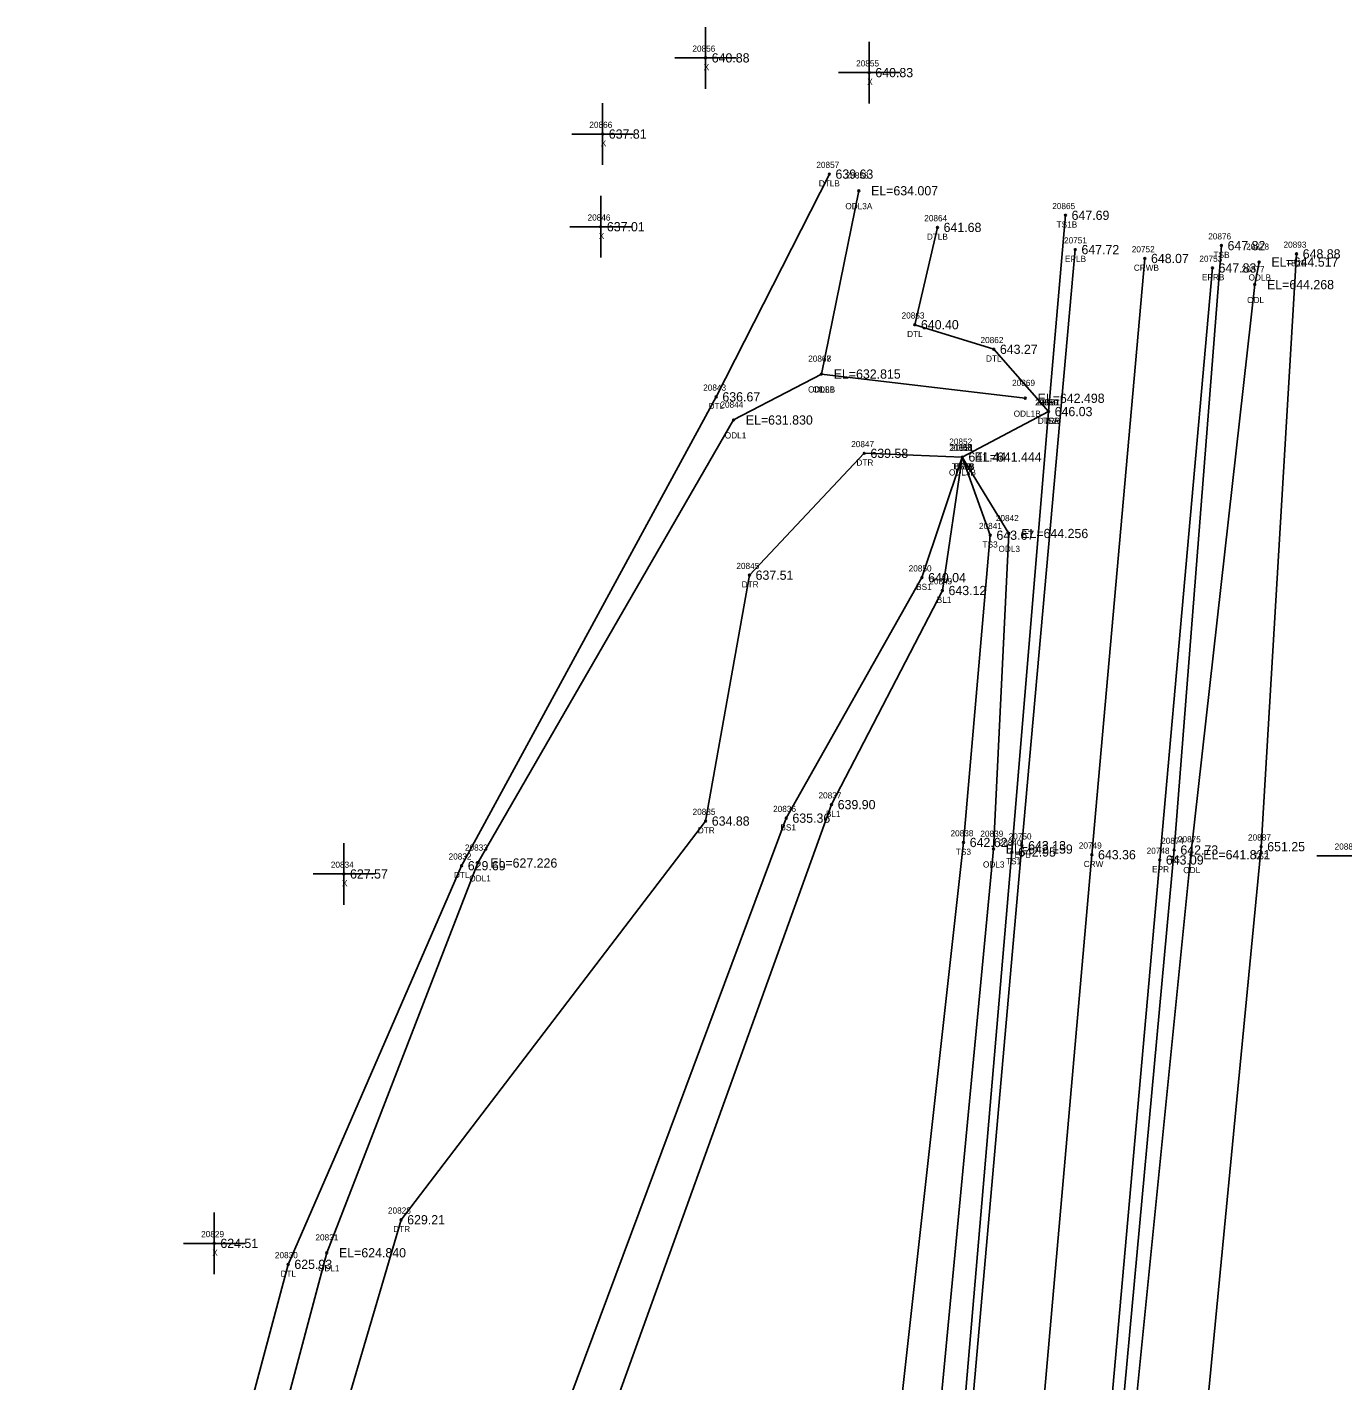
# Model space of a CAD drawing. Extents: x 1695443 to 1696344, y 1087542 to 1090645.
# Drawn here: x 1695706.6 to 1695920.2, y 1090424.7 to 1090644.5 of the extents above; entities that cross this region are included whole.
import ezdxf

# ---------------------------------------------------------------- set-up
doc = ezdxf.new("R2010")
doc.units = 0
for name, color, linetype in [('RD_DTM_BkLn1', 7, 'Continuous'), ('RD_DTM_BkLn2', 7, 'Continuous'), ('RD_DTM_BkLn_txCode', 7, 'Continuous'), ('RD_EX_H2O', 7, 'Continuous'), ('RD_EX_H2O_txCode', 7, 'Continuous'), ('RD_EX_Misc', 7, 'Continuous'), ('RD_EX_Misc_txCode', 7, 'Continuous'), ('RD_EX_Road', 7, 'Continuous'), ('RD_EX_Road_txCode', 7, 'Continuous'), ('RD_EX_TX_H2O_ELEV', 7, 'Continuous'), ('RD_EX_TX_Misc_ELEV', 7, 'Continuous'), ('RD_EX_TX_Road_ELEV', 7, 'Continuous'), ('RD_HC_Survey_ELEV', 7, 'Continuous'), ('RD_HC_Survey_txCode', 7, 'Continuous'), ('RD_SMD_Locator', 7, 'Continuous')]:
    doc.layers.add(name, color=color, linetype=linetype)

msp = doc.modelspace()

# ---------------------------------------------------------------- linework, layer by layer
at = {"layer": 'RD_DTM_BkLn1'}
for points in [[(1695813.78, 1089148.1), (1695785.55, 1089189.03), (1695758.89, 1089235.87), (1695740.64, 1089279.02), (1695725.17, 1089334.02), (1695718.27, 1089382.65), (1695717.41, 1089435.13), (1695722.03, 1089482.62), (1695732.64, 1089534.75), (1695759.85, 1089631.43), (1695787.11, 1089727.89), (1695798.89, 1089774.41), (1695810.31, 1089824.5), (1695818.49, 1089870.61), (1695825.85, 1089922.33), (1695831.69, 1089976.57), (1695835.49, 1090019.27), (1695844.06, 1090117.91), (1695852.56, 1090215.73), (1695861.78, 1090313.02), (1695870.8, 1090411.68), (1695879.44, 1090510.15), (1695888.04, 1090606.94)], [(1695751.04, 1090219.89), (1695791.94, 1090244.82), (1695767.34, 1090324.95), (1695800.6, 1090416.81), (1695837.18, 1090518.29), (1695855.17, 1090553.04), (1695858.41, 1090574.71)]]:
    msp.add_lwpolyline(points, dxfattribs=at)
at = {"layer": 'RD_DTM_BkLn2'}
for points in [[(1695816.55, 1089985.57), (1695822.06, 1090019.33), (1695830.08, 1090118.98), (1695839.03, 1090218.11), (1695848.5, 1090314.54), (1695858.08, 1090412.43), (1695866.47, 1090510.6), (1695872.4, 1090582.09), (1695875.15, 1090613.95)], [(1695859.8, 1090070.52), (1695855.89, 1090074.82), (1695858.76, 1090117.78), (1695865.52, 1090214.74), (1695874.78, 1090312.49), (1695883.57, 1090410.43), (1695892.81, 1090510.92), (1695900.47, 1090609.03)], [(1695859.8, 1090070.52), (1695863.31, 1090073.64), (1695869.86, 1090116.28), (1695876.76, 1090213.36), (1695888.73, 1090306.44), (1695897.16, 1090410.32), (1695906.91, 1090511.46), (1695912.67, 1090607.68)], [(1695751.04, 1090219.89), (1695779.04, 1090246.96), (1695759.36, 1090326.31), (1695793.36, 1090418.3), (1695829.83, 1090516.09), (1695851.86, 1090555.13), (1695858.41, 1090574.71)], [(1695816.55, 1089985.57), (1695816.58, 1090019.89), (1695824.64, 1090119.16), (1695834.2, 1090219.01), (1695837.98, 1090315.44), (1695847.83, 1090415.25), (1695858.61, 1090512.14), (1695862.95, 1090562.02), (1695858.41, 1090574.71)]]:
    msp.add_lwpolyline(points, dxfattribs=at)
at = {"layer": 'RD_EX_H2O'}
msp.add_line((1695841.6, 1090617.93), (1695835.53, 1090588.18), dxfattribs=at)
for points in [[(1695706.84, 1090232.08), (1695721.27, 1090207.48), (1695724.07, 1090225.45), (1695728.53, 1090239.62), (1695741.98, 1090247.74), (1695743.59, 1090251.5), (1695720.64, 1090337.79), (1695748.97, 1090443.66), (1695777.13, 1090508.37), (1695818.46, 1090584.48), (1695836.82, 1090620.63)], [(1695872.4, 1090582.09), (1695863.51, 1090592.2), (1695850.69, 1090596.19), (1695854.37, 1090611.98)], [(1695860.52, 1090075.19), (1695864.26, 1090116.99), (1695868.56, 1090214.89), (1695876.96, 1090312.57), (1695885.5, 1090410.04), (1695895.53, 1090510.16), (1695905.88, 1090602.7), (1695906.59, 1090606.36)], [(1695742.01, 1090022.28), (1695741.79, 1090065.32), (1695727.64, 1090116.67), (1695728.4, 1090182.12), (1695739.32, 1090221.09), (1695746.13, 1090251.36), (1695744.91, 1090257.64), (1695725.79, 1090335.12), (1695755.22, 1090445.54), (1695779.78, 1090508.81), (1695821.26, 1090580.72), (1695835.53, 1090588.18), (1695868.63, 1090584.25)], [(1695748.39, 1090023.09), (1695750.06, 1090066.34), (1695732.27, 1090115.98), (1695751.04, 1090219.89), (1695755.24, 1090253.72), (1695734.04, 1090337.88), (1695767.29, 1090450.9), (1695816.74, 1090515.62), (1695823.85, 1090555.53), (1695842.49, 1090575.31), (1695858.41, 1090574.71), (1695872.4, 1090582.09)], [(1695816.55, 1089985.57), (1695820.09, 1090019.62), (1695827.87, 1090118.57), (1695837.5, 1090218.61), (1695845.63, 1090315.02), (1695854.17, 1090413.34), (1695863.46, 1090511.07), (1695865.97, 1090562.3), (1695858.41, 1090574.71)]]:
    msp.add_lwpolyline(points, dxfattribs=at)
at = {"layer": 'RD_EX_Misc'}
for p, q in [((1695816.73, 1090634.5), (1695816.73, 1090644.5)), ((1695843.29, 1090632.11), (1695843.29, 1090642.11)), ((1695811.73, 1090639.5), (1695821.73, 1090639.5)), ((1695838.29, 1090637.11), (1695848.29, 1090637.11)), ((1695800.02, 1090622.14), (1695800.02, 1090632.14)), ((1695795.02, 1090627.14), (1695805.02, 1090627.14)), ((1695799.71, 1090607.09), (1695799.71, 1090617.09)), ((1695794.71, 1090612.09), (1695804.71, 1090612.09)), ((1695758.01, 1090502.03), (1695758.01, 1090512.03)), ((1695915.97, 1090509.98), (1695925.97, 1090509.98)), ((1695753.01, 1090507.03), (1695763.01, 1090507.03)), ((1695736.96, 1090442.07), (1695736.96, 1090452.07)), ((1695731.96, 1090447.07), (1695741.96, 1090447.07))]:
    msp.add_line(p, q, dxfattribs=at)
at = {"layer": 'RD_EX_Road'}
for points in [[(1695813.78, 1089148.1), (1695805.56, 1089142.08), (1695776.44, 1089183.94), (1695749.27, 1089231.88), (1695730.49, 1089275.72), (1695714.87, 1089332.12), (1695707.87, 1089381.72), (1695706.58, 1089435.34), (1695711.58, 1089484.26), (1695722.15, 1089537.59), (1695749.04, 1089634.88), (1695776.11, 1089730.43), (1695788.13, 1089777.42), (1695798.89, 1089826.76), (1695807.1, 1089870.03), (1695814.71, 1089923.3), (1695820.51, 1089978.16), (1695824.04, 1090019.79), (1695832.76, 1090119.06), (1695841.25, 1090216.76), (1695850.36, 1090314.41), (1695859.24, 1090411.82), (1695868.09, 1090511.63), (1695876.75, 1090608.38)], [(1695728.69, 1089383.6), (1695727.9, 1089434.83), (1695732.68, 1089480.1), (1695743.4, 1089531.84), (1695770.35, 1089628.36), (1695797.63, 1089725.22), (1695809.49, 1089772.37), (1695818.34, 1089811.57), (1695820.65, 1089823.41), (1695822.99, 1089835.26), (1695829.18, 1089869.37), (1695836.32, 1089920.97), (1695842.44, 1089975.46), (1695846.49, 1090018.55), (1695849.32, 1090055.39), (1695850.91, 1090072.92), (1695855.09, 1090117.49), (1695863.53, 1090214.93), (1695872.56, 1090312.44), (1695881.69, 1090410.78), (1695890.45, 1090509.3), (1695899.01, 1090605.4)]]:
    msp.add_lwpolyline(points, dxfattribs=at)
at = {"layer": 'RD_SMD_Locator'}
for centre in [(1695816.73, 1090639.5), (1695843.29, 1090637.11), (1695800.02, 1090627.14), (1695836.82, 1090620.63), (1695841.6, 1090617.93), (1695875.15, 1090613.95), (1695799.71, 1090612.09), (1695854.37, 1090611.98), (1695876.75, 1090608.38), (1695900.47, 1090609.03), (1695888.04, 1090606.94), (1695906.59, 1090606.36), (1695912.67, 1090607.68), (1695899.01, 1090605.4), (1695905.88, 1090602.7), (1695850.69, 1090596.19), (1695863.51, 1090592.2), (1695835.53, 1090588.18), (1695835.53, 1090588.18), (1695818.46, 1090584.48), (1695868.63, 1090584.25), (1695872.4, 1090582.09), (1695872.4, 1090582.09), (1695872.4, 1090582.09), (1695821.26, 1090580.72), (1695842.49, 1090575.31), (1695858.41, 1090574.71), (1695858.41, 1090574.71), (1695858.41, 1090574.71), (1695858.41, 1090574.71), (1695858.41, 1090574.71), (1695862.95, 1090562.02), (1695865.97, 1090562.3), (1695823.85, 1090555.53), (1695851.86, 1090555.13), (1695855.17, 1090553.04), (1695837.18, 1090518.29), (1695816.74, 1090515.62), (1695829.83, 1090516.09), (1695858.61, 1090512.14), (1695868.09, 1090511.63), (1695906.91, 1090511.46), (1695863.46, 1090511.07), (1695866.47, 1090510.6), (1695879.44, 1090510.15), (1695890.45, 1090509.3), (1695892.81, 1090510.92), (1695895.53, 1090510.16), (1695758.01, 1090507.03), (1695777.13, 1090508.37), (1695779.78, 1090508.81), (1695767.29, 1090450.9), (1695736.96, 1090447.07), (1695755.22, 1090445.54), (1695748.97, 1090443.66)]:
    msp.add_circle(centre, 0.15, dxfattribs=at)

# ---------------------------------------------------------------- texts
at = {"layer": 'RD_DTM_BkLn_txCode'}
for s, p in [('20865', (1695873.01, 1090614.95)), ('TS1B', (1695873.72, 1090611.95)), ('20876', (1695898.33, 1090610.03)), ('TSB', (1695899.2, 1090607.03)), ('20893', (1695910.55, 1090608.68)), ('TS2B', (1695910.95, 1090605.68)), ('20860', (1695870.22, 1090583.09)), ('TS1', (1695871.44, 1090580.09)), ('20853', (1695856.29, 1090575.71)), ('20854', (1695856.29, 1090575.71)), ('20851', (1695856.57, 1090575.71)), ('TS3B', (1695856.69, 1090572.71)), ('BS1B', (1695856.99, 1090572.71)), ('BL1B', (1695857.01, 1090572.71)), ('20841', (1695861.11, 1090563.02)), ('TS3', (1695861.7, 1090560.02)), ('20850', (1695849.7, 1090556.13)), ('BS1', (1695850.91, 1090553.13)), ('20849', (1695853.05, 1090554.04)), ('BL1', (1695854.25, 1090551.04)), ('20837', (1695835.06, 1090519.29)), ('20836', (1695827.69, 1090517.09)), ('BL1', (1695836.26, 1090516.29)), ('BS1', (1695828.88, 1090514.09)), ('20838', (1695856.49, 1090513.14)), ('20887', (1695904.79, 1090512.46)), ('20840', (1695864.31, 1090511.6)), ('20874', (1695890.69, 1090511.92)), ('TS3', (1695857.37, 1090510.14)), ('TS1', (1695865.51, 1090508.6)), ('TS', (1695892.02, 1090508.92)), ('TS2', (1695905.66, 1090509.46))]:
    msp.add_text(s, height=1, dxfattribs=at).set_placement(p)
at = {"layer": 'RD_EX_H2O_txCode'}
for s, p in [('20857', (1695834.71, 1090621.63)), ('DTLB', (1695835.11, 1090618.63)), ('20858', (1695839.48, 1090619.93)), ('ODL3A', (1695839.42, 1090614.93)), ('20864', (1695852.23, 1090612.98)), ('DTLB', (1695852.65, 1090609.98)), ('20878', (1695904.48, 1090608.36)), ('20877', (1695903.76, 1090604.7)), ('ODLB', (1695904.88, 1090603.36)), ('ODL', (1695904.64, 1090599.7)), ('20863', (1695848.55, 1090597.19)), ('DTL', (1695849.45, 1090594.19)), ('20862', (1695861.36, 1090593.2)), ('20867', (1695833.39, 1090590.18)), ('20868', (1695833.39, 1090590.18)), ('DTL', (1695862.26, 1090590.2)), ('20843', (1695816.34, 1090585.48)), ('ODL3B', (1695833.37, 1090585.18)), ('ODL1', (1695834.12, 1090585.18)), ('20869', (1695866.49, 1090586.25)), ('20859', (1695870.28, 1090583.09)), ('20861', (1695870.54, 1090583.09)), ('DTL', (1695817.21, 1090582.48)), ('20844', (1695819.14, 1090582.72)), ('ODL1B', (1695866.75, 1090581.25)), ('DTRB', (1695870.66, 1090580.09)), ('DTLA', (1695870.67, 1090580.09)), ('ODL1', (1695819.85, 1090577.72)), ('20847', (1695840.37, 1090576.31)), ('20852', (1695856.29, 1090576.71)), ('20848', (1695856.29, 1090575.71)), ('DTR', (1695841.22, 1090573.31)), ('DTR', (1695857.14, 1090572.71)), ('ODL3B', (1695856.24, 1090571.71)), ('20842', (1695863.85, 1090564.3)), ('ODL3', (1695864.28, 1090559.3)), ('20845', (1695821.73, 1090556.53)), ('DTR', (1695822.59, 1090553.53)), ('20835', (1695814.62, 1090516.62)), ('DTR', (1695815.47, 1090513.62)), ('20839', (1695861.34, 1090513.07)), ('20833', (1695777.66, 1090510.81)), ('20875', (1695893.41, 1090512.16)), ('20832', (1695775.01, 1090509.37)), ('ODL3', (1695861.76, 1090508.07)), ('DTL', (1695775.88, 1090506.37)), ('ODL', (1695894.28, 1090507.16)), ('ODL1', (1695778.37, 1090505.81)), ('20828', (1695765.17, 1090451.9)), ('DTR', (1695766.02, 1090448.9)), ('20831', (1695753.39, 1090447.54)), ('20830', (1695746.81, 1090444.66)), ('ODL1', (1695753.81, 1090442.54)), ('DTL', (1695747.72, 1090441.66))]:
    msp.add_text(s, height=1, dxfattribs=at).set_placement(p)
at = {"layer": 'RD_EX_Misc_txCode'}
for s, p in [('20856', (1695814.59, 1090640.5)), ('20855', (1695841.17, 1090638.11)), ('X', (1695816.42, 1090637.5)), ('X', (1695842.97, 1090635.11)), ('20866', (1695797.86, 1090628.14)), ('X', (1695799.71, 1090625.14)), ('20846', (1695797.57, 1090613.09)), ('X', (1695799.4, 1090610.09)), ('20888', (1695918.85, 1090510.98)), ('20834', (1695755.89, 1090508.03)), ('X', (1695757.7, 1090505.03)), ('20829', (1695734.84, 1090448.07)), ('X', (1695736.64, 1090445.07))]:
    msp.add_text(s, height=1, dxfattribs=at).set_placement(p)
at = {"layer": 'RD_EX_Road_txCode'}
for s, p in [('20751', (1695874.92, 1090609.38)), ('EPLB', (1695875.08, 1090606.38)), ('20753', (1695896.89, 1090606.4)), ('EPRB', (1695897.31, 1090603.4)), ('20750', (1695865.93, 1090512.63)), ('20748', (1695888.33, 1090510.3)), ('EPL', (1695866.89, 1090509.63)), ('EPR', (1695889.22, 1090507.3))]:
    msp.add_text(s, height=1, dxfattribs=at).set_placement(p)
at = {"layer": 'RD_EX_TX_H2O_ELEV'}
for s, p in [('639.63', (1695837.82, 1090619.88)), ('EL=634.007', (1695843.6, 1090617.18)), ('641.68', (1695855.37, 1090611.23)), ('EL=644.517', (1695908.59, 1090605.61)), ('EL=644.268', (1695907.88, 1090601.95)), ('640.40', (1695851.69, 1090595.44)), ('643.27', (1695864.51, 1090591.45)), ('EL=632.815', (1695837.53, 1090587.43)), ('EL=632.815', (1695837.53, 1090587.43)), ('636.67', (1695819.46, 1090583.73)), ('EL=642.498', (1695870.63, 1090583.5)), ('646.03', (1695873.4, 1090581.34)), ('646.03', (1695873.4, 1090581.34)), ('EL=631.830', (1695823.26, 1090579.97)), ('639.58', (1695843.49, 1090574.56)), ('641.44', (1695859.41, 1090573.96)), ('EL=641.444', (1695860.41, 1090573.96)), ('EL=644.256', (1695867.97, 1090561.55)), ('637.51', (1695824.85, 1090554.78)), ('634.88', (1695817.74, 1090514.87)), ('EL=642.159', (1695865.46, 1090510.32)), ('629.69', (1695778.13, 1090507.62)), ('EL=627.226', (1695781.78, 1090508.06)), ('EL=641.821', (1695897.53, 1090509.41)), ('629.21', (1695768.29, 1090450.15)), ('EL=624.840', (1695757.22, 1090444.79)), ('625.93', (1695749.97, 1090442.91))]:
    msp.add_text(s, height=1.5, dxfattribs=at).set_placement(p)
at = {"layer": 'RD_EX_TX_Misc_ELEV'}
for s, p in [('640.88', (1695817.73, 1090638.75)), ('640.83', (1695844.29, 1090636.36)), ('637.81', (1695801.02, 1090626.39)), ('647.69', (1695876.15, 1090613.2)), ('637.01', (1695800.71, 1090611.34)), ('647.82', (1695901.47, 1090608.28)), ('648.88', (1695913.67, 1090606.93)), ('646.03', (1695873.4, 1090581.34)), ('641.44', (1695859.41, 1090573.96)), ('641.44', (1695859.41, 1090573.96)), ('641.44', (1695859.41, 1090573.96)), ('643.67', (1695863.95, 1090561.27)), ('640.04', (1695852.86, 1090554.38)), ('643.12', (1695856.17, 1090552.29)), ('639.90', (1695838.18, 1090517.54)), ('635.36', (1695830.83, 1090515.34)), ('642.62', (1695859.61, 1090511.39)), ('642.95', (1695867.47, 1090509.85)), ('642.73', (1695893.81, 1090510.17)), ('651.25', (1695907.91, 1090510.71)), ('627.57', (1695759.01, 1090506.28)), ('624.51', (1695737.96, 1090446.32))]:
    msp.add_text(s, height=1.5, dxfattribs=at).set_placement(p)
at = {"layer": 'RD_EX_TX_Road_ELEV'}
for s, p in [('647.72', (1695877.75, 1090607.63)), ('647.83', (1695900.01, 1090604.65)), ('643.13', (1695869.09, 1090510.88)), ('643.09', (1695891.45, 1090508.55))]:
    msp.add_text(s, height=1.5, dxfattribs=at).set_placement(p)
at = {"layer": 'RD_HC_Survey_ELEV'}
for s, p in [('648.07', (1695889.04, 1090606.19)), ('643.36', (1695880.44, 1090509.4))]:
    msp.add_text(s, height=1.5, dxfattribs=at).set_placement(p)
at = {"layer": 'RD_HC_Survey_txCode'}
for s, p in [('20752', (1695885.92, 1090607.94)), ('CRWB', (1695886.25, 1090604.94)), ('20749', (1695877.32, 1090511.15)), ('CRW', (1695878.12, 1090508.15))]:
    msp.add_text(s, height=1, dxfattribs=at).set_placement(p)

doc.saveas('drawing.dxf')
